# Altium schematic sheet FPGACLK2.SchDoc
size A; PageSetup: Record=PageOptions|SelectedOnly=False|CenterHorizontal=True|CenterVertical=True|PrintScale=1.38|XCorrection=1.00|YCorrection=1.00|PrintKind=0|BorderSize=5000000|LeftOffset=0|BottomOffset=0|Orientation=2|PaperLength=1000|PaperWidth=1000|Scale=100|PaperSource=15|PrintQuality=600|MediaType=1|DitherType=10|PaperKind=11x17|PrintScaleMode=1
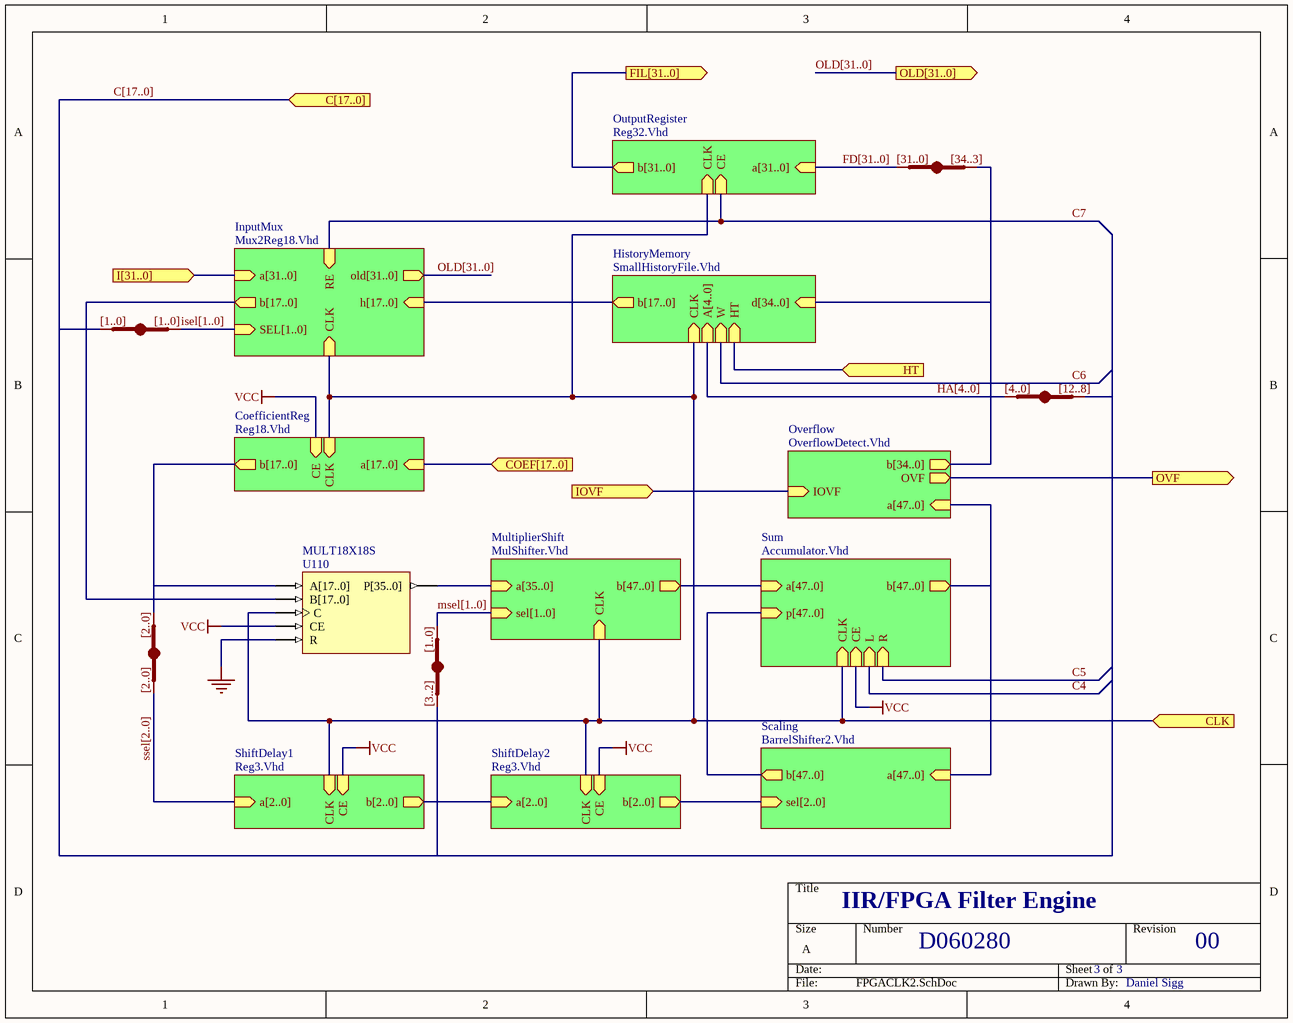
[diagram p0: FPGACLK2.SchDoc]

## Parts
JB_C25  IndexA: [31..0]  IndexB: [34..3]  (hidden comment: JB)
JB_C26  IndexA: [1..0]  (hidden comment: JB)
JB_C27  IndexA: [4..0]  IndexB: [12..8]  (hidden comment: JB)
JB_C28  IndexA: [2..0]  (hidden comment: JB)
JB_C29  IndexA: [3..2]  IndexB: [1..0]  (hidden comment: JB)
U110  MULT18X18S

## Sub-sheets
CoefficientReg = Reg18.Vhd: a[17..0] (in), b[17..0] (out), CLK (in), CE (in)
HistoryMemory = SmallHistoryFile.Vhd: d[34..0] (in), b[17..0] (out), CLK (in), A[4..0] (in), W (in), HT (in)
InputMux = Mux2Reg18.Vhd: a[31..0] (in), b[17..0] (out), h[17..0] (in), CLK (in), SEL[1..0] (in), old[31..0] (out), RE (in)
MultiplierShift = MulShifter.Vhd: a[35..0] (in), b[47..0] (out), sel[1..0] (in), CLK (in)
OutputRegister = Reg32.Vhd: a[31..0] (in), b[31..0] (out), CLK (in), CE (in)
Overflow = OverflowDetect.Vhd: a[47..0] (in), b[34..0] (out), IOVF (in), OVF (out)
Scaling = BarrelShifter2.Vhd: a[47..0] (in), b[47..0] (out), sel[2..0] (in)
ShiftDelay1 = Reg3.Vhd: a[2..0] (in), b[2..0] (out), CLK (in), CE (in)
ShiftDelay2 = Reg3.Vhd: a[2..0] (in), b[2..0] (out), CLK (in), CE (in)
Sum = Accumulator.Vhd: a[47..0] (in), b[47..0] (out), p[47..0] (in), CLK (in), CE (in), L (in), R (in)

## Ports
C[17..0] (in), CLK (in), COEF[17..0] (in), FIL[31..0] (out), HT (in), I[31..0] (in), IOVF (in), OLD[31..0] (out), OVF (out)

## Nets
GND: U110.R
VCC: U110.CE ; sheet Sum/CE, sheet CoefficientReg/CE, sheet ShiftDelay1/CE, sheet ShiftDelay2/CE
C7: sheet InputMux/RE, sheet OutputRegister/CE
CLK: U110.C ; port CLK, sheet Sum/CLK, sheet MultiplierShift/CLK, sheet InputMux/CLK, sheet CoefficientReg/CLK, sheet HistoryMemory/CLK, sheet OutputRegister/CLK, sheet ShiftDelay1/CLK, sheet ShiftDelay2/CLK
HT: port HT, sheet HistoryMemory/HT
IOVF: port IOVF, sheet Overflow/IOVF
OVF: port OVF, sheet Overflow/OVF

Not connected (* = marked no-connect by the designer): JB_C25 A[0..0] B[0..0]; JB_C26 A[0..0] B[0..0]; JB_C27 A[0..0] B[0..0]; JB_C28 A[0..0] B[0..0]; JB_C29 A[0..0] B[0..0]; U110 A[17..0] B[17..0] P[35..0]

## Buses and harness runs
bus C[17..0] = port C[17..0]
bus FD[31..0] = sheet OutputRegister/a[31..0]
bus HA[4..0] = sheet HistoryMemory/A[4..0]
bus isel[1..0] = sheet InputMux/SEL[1..0]
bus msel[1..0] = sheet MultiplierShift/sel[1..0]
bus OLD[31..0] = port OLD[31..0]
bus OLD[31..0] = sheet InputMux/old[31..0]
bus port COEF[17..0] = sheet CoefficientReg/a[17..0]
bus port FIL[31..0] = sheet OutputRegister/b[31..0]
bus port I[31..0] = sheet InputMux/a[31..0]
bus sheet HistoryMemory/b[17..0] = sheet InputMux/h[17..0]
bus sheet HistoryMemory/d[34..0] = sheet Overflow/b[34..0]
bus sheet MultiplierShift/b[47..0] = sheet Sum/a[47..0]
bus sheet Overflow/a[47..0] = sheet Scaling/a[47..0] = sheet Sum/b[47..0]
bus sheet Scaling/b[47..0] = sheet Sum/p[47..0]
bus sheet Scaling/sel[2..0] = sheet ShiftDelay2/b[2..0]
bus sheet ShiftDelay1/b[2..0] = sheet ShiftDelay2/a[2..0]
bus ssel[2..0] = sheet ShiftDelay1/a[2..0]

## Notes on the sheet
- IIR/FPGA Filter Engine
- D060280
- 3
- 00
- Daniel Sigg

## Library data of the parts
JB_C25-JB_C29 = JB: System BUS Joiner
U110 = MULT18X18S: 18 x 18 Signed Multiplier -- Registered Version; FPGAVendor: Xilinx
